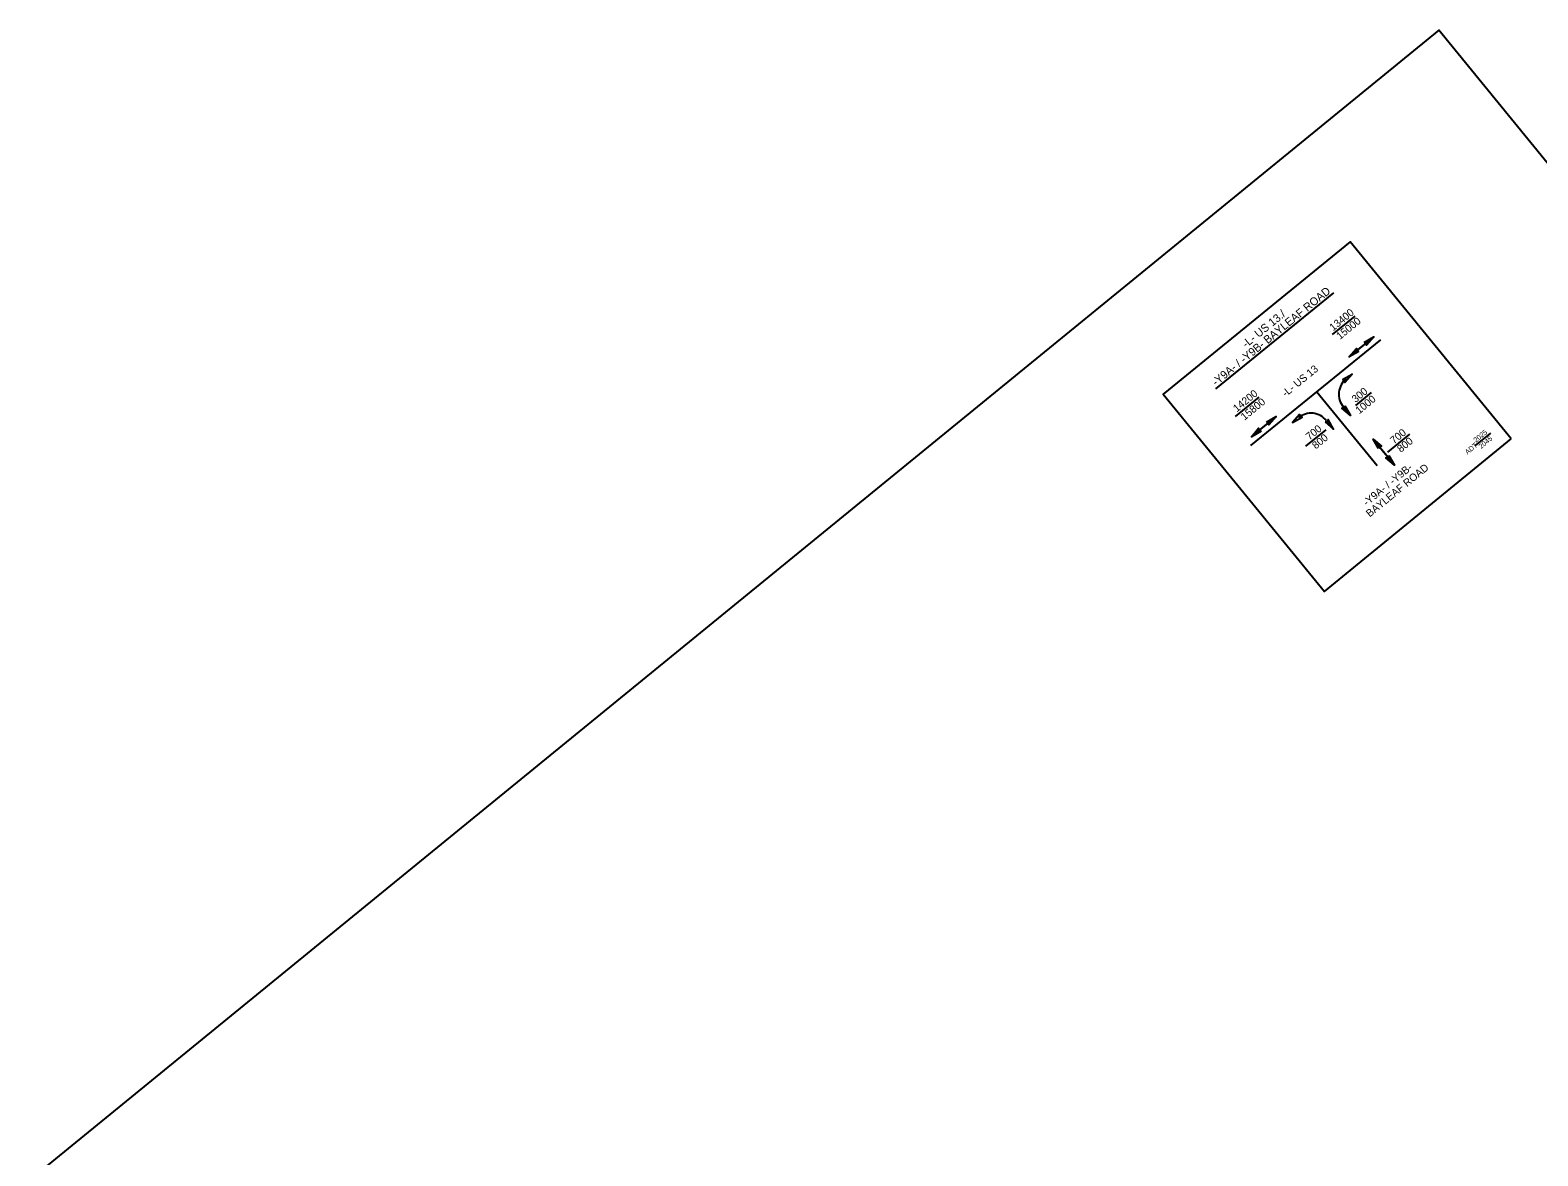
# Model space of a CAD drawing. Extents: x 2324217 to 2325994, y 600007 to 601705.
# Drawn here: x 2324217 to 2325221, y 600837 to 601587 of the extents above; entities that cross this region are included whole.
import ezdxf

# ---------------------------------------------------------------- set-up
doc = ezdxf.new("R2010")
doc.units = 0
for name, color, linetype in [('TC CONSTRUCTION TEMP PAVEMENT BREAKDOWN LANE SHADE', 7, 'Continuous'), ('TC DEV HIGH LEVEL WARNING', 7, 'Continuous'), ('TC DEV SIGN ARROW BOARD YELLOW', 7, 'Continuous')]:
    doc.layers.add(name, color=color, linetype=linetype)

msp = doc.modelspace()

# ---------------------------------------------------------------- linework, layer by layer
at = {"layer": 'TC CONSTRUCTION TEMP PAVEMENT BREAKDOWN LANE SHADE'}
msp.add_lwpolyline([(2324881.4, 600007.4), (2325965.9, 600892.8), (2325920.8, 600948), (2325411.6, 601571.7), (2325265, 601452.1), (2325155.3, 601586.5), (2324217.4, 600820.8)], close=True, dxfattribs=at)
at = {"layer": 'TC DEV HIGH LEVEL WARNING'}
for p, q in [((2325006.8, 601347.5), (2325085.4, 601411.6)), ((2325084.6, 601383.8), (2325099.6, 601396)), ((2325030.2, 601309.7), (2325116.6, 601380.3)), ((2325095.6, 601368.8), (2325107.1, 601378.2)), ((2325112, 601382.2), (2325100.5, 601372.8)), ((2325074.1, 601345.6), (2325114.3, 601296.5)), ((2325019.9, 601329.2), (2325035.6, 601342)), ((2325091.7, 601335.7), (2325096.4, 601329.8)), ((2325100, 601336.5), (2325110.4, 601345)), ((2325046.9, 601329.1), (2325035.4, 601319.7)), ((2325080.4, 601326.4), (2325085.1, 601320.6)), ((2325030.5, 601315.6), (2325042, 601325.1)), ((2325066.7, 601309.3), (2325080.2, 601320.3)), ((2325121.3, 601305.3), (2325136, 601317.4)), ((2325179.8, 601309.8), (2325189.9, 601318)), ((2325111.6, 601314.1), (2325121, 601302.6)), ((2325125.7, 601296.8), (2325116.3, 601308.3))]:
    msp.add_line(p, q, dxfattribs=at)
for points in [[(2325105.6, 601378.5), (2325112, 601382.2), (2325107.2, 601376.6), (2325107.1, 601378.2)], [(2325102, 601372.5), (2325095.6, 601368.8), (2325100.4, 601374.4), (2325100.5, 601372.8)], [(2325091.1, 601353.7), (2325097.5, 601357.4), (2325092.7, 601351.8), (2325092.6, 601353.4)], [(2325092.8, 601336.2), (2325096.4, 601329.8), (2325090.8, 601334.6), (2325092.4, 601334.7)], [(2325040.6, 601325.4), (2325046.9, 601329.1), (2325042.1, 601323.5), (2325042, 601325.1)], [(2325062.8, 601330.6), (2325057.9, 601325.1), (2325064.4, 601328.7), (2325062.8, 601329.1)], [(2325079.6, 601325.5), (2325085.1, 601320.6), (2325081.6, 601327.1), (2325081.1, 601325.5)], [(2325036.9, 601319.3), (2325030.5, 601315.6), (2325035.3, 601321.3), (2325035.4, 601319.7)], [(2325115.2, 601307.7), (2325111.6, 601314.1), (2325117.2, 601309.3), (2325115.6, 601309.2)], [(2325122, 601303.2), (2325125.7, 601296.8), (2325120.1, 601301.6), (2325121.7, 601301.7)]]:
    msp.add_lwpolyline(points, close=True, dxfattribs=at)
for centre, start, end in [((2325101.9, 601344), 129.2543, 219.2545), ((2325070.2, 601318.1), 39.2014, 129.2017)]:
    msp.add_arc(centre, 13.2, start, end, dxfattribs=at)
at = {"layer": 'TC DEV SIGN ARROW BOARD YELLOW'}
msp.add_lwpolyline([(2325203.5, 601314.2), (2325096.2, 601445.5), (2324971.8, 601344), (2325079.1, 601212.6)], close=True, dxfattribs=at)

# ---------------------------------------------------------------- texts
at = {"layer": 'TC DEV HIGH LEVEL WARNING'}
for s, height, rotation, p in [('-Y9A- / -Y9B- BAYLEAF ROAD', 5.333, 39.1922, (2325006.9, 601349.2)), ('-L- US 13./', 5.333, 39.1922, (2325027, 601374.6)), ('13400', 5, 39.1922, (2325084.9, 601385.8)), ('15000', 5, 39.1922, (2325089.5, 601380.1)), ('-L- US 13', 5, 39.1922, (2325053.3, 601341.9)), ('14200', 5, 39.1922, (2325020.8, 601331.8)), ('300', 5, 39.1922, (2325099.8, 601338)), ('15800', 5, 39.1922, (2325025.9, 601326.3)), ('1000', 5, 39.1922, (2325102.3, 601330.5)), ('700', 5, 39.1922, (2325069.2, 601313.1)), ('800', 5, 39.1922, (2325073.4, 601307.1)), ('700', 5, 39.1922, (2325125.4, 601310.5)), ('2025', 3.33, 39.2016, (2325180, 601311.6)), ('2045', 3.33, 39.2016, (2325183.4, 601307.4)), ('800', 5, 39.1922, (2325130, 601304.9)), ('ADT', 3.33, 39.2016, (2325174.3, 601303.6)), ('-Y9A- / -Y9B-', 5, 39.1922, (2325107.3, 601269.2)), ('BAYLEAF ROAD', 5, 39.1922, (2325109.3, 601261.8))]:
    msp.add_text(s, height=height, rotation=rotation, dxfattribs=at).set_placement(p)

doc.saveas('drawing.dxf')
